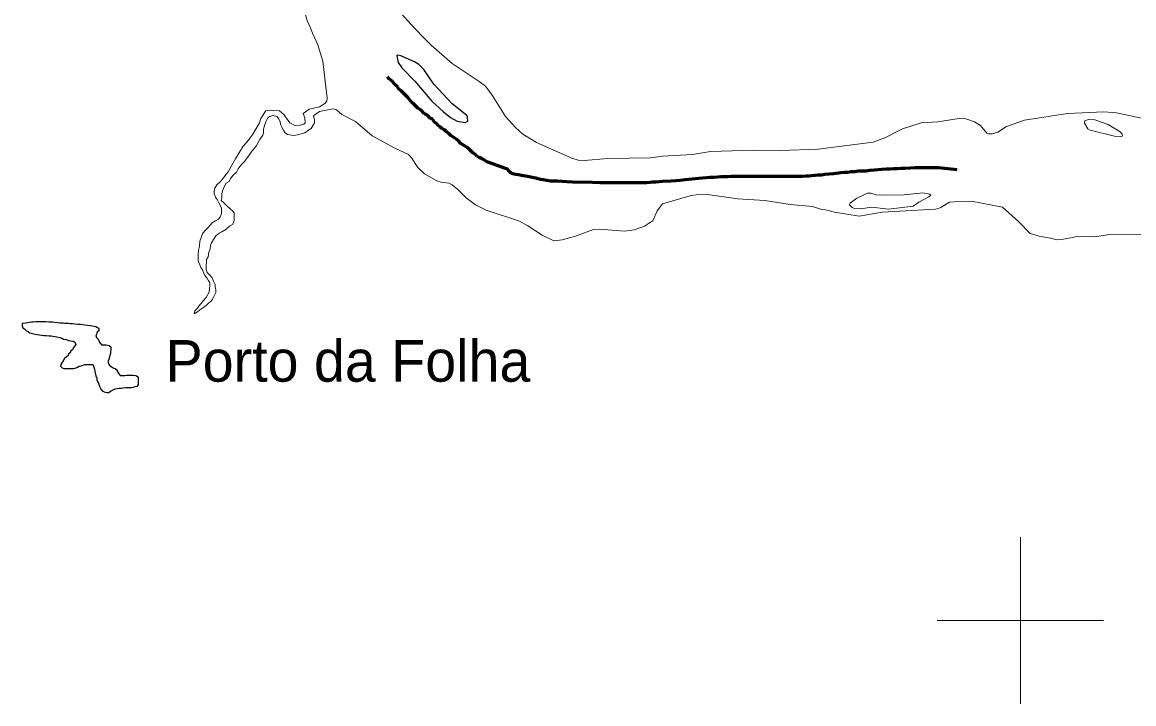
# Model space of a CAD drawing. Extents: x 553962 to 842807, y 8883888 to 9032388.
# Drawn here: x 687999 to 701363, y 8899000 to 8907189 of the extents above; entities that cross this region are included whole.
import ezdxf

# ---------------------------------------------------------------- set-up
doc = ezdxf.new("R2010")
doc.units = 0
doc.header["$LTSCALE"] = 200
doc.linetypes.add('LONG_DASH_SHORT_DASH', pattern=[9.9, 6, -1.2, 1.5, -1.2])
for name, color, linetype, lineweight in [('2', 7, 'Continuous', 13), ('21', 7, 'Continuous', 25), ('24', 7, 'Continuous', 25), ('25', 7, 'Continuous', 13), ('7', 7, 'Continuous', 90)]:
    doc.layers.add(name, color=color, linetype=linetype, lineweight=lineweight)
doc.layers.add('41', color=7, linetype='Continuous')

msp = doc.modelspace()

# ---------------------------------------------------------------- linework, layer by layer
at = {"layer": '2'}
for p, q in [((700000, 8899000), (700000, 8901000)), ((699000, 8900000), (701000, 8900000))]:
    msp.add_line(p, q, dxfattribs=at)
at = {"layer": '21', "lineweight": 13}
for points in [[(687999.3, 8903568.5), (688042.6, 8903573.7), (688065.5, 8903578.8), (688085.8, 8903581.3), (688111.3, 8903586.4), (688131.6, 8903586.4), (688162.2, 8903589), (688197.8, 8903589), (688218.1, 8903589), (688251.2, 8903589), (688281.8, 8903589), (688319.9, 8903586.4), (688363.2, 8903583.9), (688386.1, 8903581.3), (688424.2, 8903578.8), (688454.8, 8903573.7), (688490.4, 8903573.7), (688510.8, 8903571.1), (688536.2, 8903568.6), (688556.6, 8903568.6), (688576.9, 8903566), (688602.4, 8903563.4), (688632.9, 8903560.9), (688666, 8903558.3), (688701.6, 8903555.8), (688722, 8903553.2), (688783, 8903545.6), (688818.7, 8903540.4), (688841.6, 8903537.9), (688861.9, 8903532.8), (688882.3, 8903527.7), (688905.2, 8903517.4), (688925.5, 8903509.8), (688925.5, 8903489.3), (688905.2, 8903471.4), (688895, 8903440.8), (688887.4, 8903420.3), (688895, 8903397.3), (688915.4, 8903376.8), (688928.1, 8903348.7), (688943.4, 8903328.3), (688961.2, 8903307.8), (688984.1, 8903307.8), (689009.6, 8903307.8), (689045.2, 8903300.2), (689068.1, 8903282.3), (689068.1, 8903251.6), (689065.6, 8903231.2), (689065.6, 8903210.7), (689055.4, 8903190.2), (689052.9, 8903167.2), (689037.6, 8903118.7), (689037.6, 8903098.2), (689045.3, 8903077.8), (689068.2, 8903047.1), (689093.6, 8903034.3), (689116.5, 8903024.1), (689139.5, 8903006.2), (689154.7, 8902985.8), (689164.9, 8902965.3), (689185.3, 8902942.3), (689208.2, 8902942.3), (689233.6, 8902942.3), (689254, 8902944.9), (689282, 8902944.9), (689307.4, 8902944.9), (689332.8, 8902944.9), (689365.9, 8902939.8), (689396.5, 8902921.9), (689396.5, 8902886.1), (689396.5, 8902858), (689396.5, 8902837.5), (689383.8, 8902817.1), (689358.3, 8902811.9), (689338, 8902804.3), (689317.6, 8902801.7), (689287.1, 8902799.2), (689266.8, 8902799.2), (689243.8, 8902799.2), (689213.3, 8902796.6), (689193, 8902794.1), (689165, 8902791.5), (689142.1, 8902788.9), (689116.6, 8902783.8), (689093.7, 8902773.6), (689068.3, 8902758.3), (689037.8, 8902740.4), (689017.4, 8902740.4), (688994.5, 8902742.9), (688964, 8902755.7), (688943.6, 8902778.7), (688933.4, 8902804.3), (688923.2, 8902827.3), (688915.6, 8902852.8), (688905.4, 8902873.3), (688895.2, 8902893.7), (688895.2, 8902914.2), (688885, 8902939.7), (688877.4, 8902975.5), (688872.3, 8902996), (688867.2, 8903019)], [(688867.2, 8903019), (688857, 8903054.8), (688849.4, 8903075.2), (688826.5, 8903077.8), (688806.1, 8903077.8), (688775.6, 8903077.8), (688752.7, 8903075.2), (688732.3, 8903067.6), (688706.9, 8903062.4), (688684, 8903054.8), (688663.6, 8903044.5), (688635.6, 8903034.3), (688615.3, 8903029.2), (688587.3, 8903026.7), (688556.8, 8903026.7), (688531.3, 8903026.7), (688500.8, 8903029.2), (688480.4, 8903036.9), (688457.5, 8903054.8), (688462.6, 8903077.8), (688475.3, 8903098.2), (688490.6, 8903121.2), (688508.4, 8903146.8), (688531.3, 8903167.2), (688551.6, 8903185.1), (688556.7, 8903205.6), (688577.1, 8903218.4), (688584.7, 8903238.8), (688605, 8903254.2), (688617.7, 8903279.7), (688633, 8903300.2), (688643.2, 8903320.6), (688633, 8903346.2), (688612.6, 8903356.4), (688584.6, 8903361.5), (688556.6, 8903366.6), (688528.6, 8903376.8), (688495.6, 8903381.9), (688475.2, 8903392.2), (688452.3, 8903399.8), (688416.7, 8903407.5), (688396.3, 8903412.6), (688368.3, 8903417.7), (688348, 8903420.3), (688322.5, 8903422.8), (688286.9, 8903425.4), (688264, 8903425.4), (688230.9, 8903430.5), (688208, 8903433.1), (688177.5, 8903438.2), (688154.6, 8903440.7), (688124.1, 8903448.4), (688091, 8903458.6), (688070.6, 8903471.4), (688050.2, 8903479.1), (688029.9, 8903499.5), (688007, 8903517.4), (687999.3, 8903543), (687999.3, 8903568.5)]]:
    msp.add_lwpolyline(points, dxfattribs=at)
at = {"layer": '21'}
for points in [[(688867.2, 8903019), (688872.3, 8902996), (688877.4, 8902975.5), (688885, 8902939.7), (688895.2, 8902914.2), (688895.2, 8902893.7), (688905.4, 8902873.3), (688915.6, 8902852.8), (688923.2, 8902827.3), (688933.4, 8902804.3), (688943.6, 8902778.7), (688964, 8902755.7), (688994.5, 8902742.9), (689017.4, 8902740.4), (689037.8, 8902740.4), (689068.3, 8902758.3), (689093.7, 8902773.6), (689116.6, 8902783.8), (689142.1, 8902788.9), (689165, 8902791.5), (689193, 8902794.1), (689213.3, 8902796.6), (689243.8, 8902799.2), (689266.8, 8902799.2), (689287.1, 8902799.2), (689317.6, 8902801.7), (689338, 8902804.3), (689358.3, 8902811.9), (689383.8, 8902817.1), (689396.5, 8902837.5), (689396.5, 8902858), (689396.5, 8902886.1), (689396.5, 8902921.9), (689365.9, 8902939.8), (689332.8, 8902944.9), (689307.4, 8902944.9), (689282, 8902944.9), (689254, 8902944.9), (689233.6, 8902942.3), (689208.2, 8902942.3), (689185.3, 8902942.3), (689164.9, 8902965.3), (689154.7, 8902985.8), (689139.5, 8903006.2), (689116.5, 8903024.1), (689093.6, 8903034.3), (689068.2, 8903047.1), (689045.3, 8903077.8), (689037.6, 8903098.2), (689037.6, 8903118.7), (689052.9, 8903167.2), (689055.4, 8903190.2), (689065.6, 8903210.7), (689065.6, 8903231.2), (689068.1, 8903251.6), (689068.1, 8903282.3), (689045.2, 8903300.2), (689009.6, 8903307.8), (688984.1, 8903307.8), (688961.2, 8903307.8), (688943.4, 8903328.3), (688928.1, 8903348.7), (688915.4, 8903376.8), (688895, 8903397.3), (688887.4, 8903420.3), (688895, 8903440.8), (688905.2, 8903471.4), (688925.5, 8903489.3), (688925.5, 8903509.8), (688905.2, 8903517.4), (688882.3, 8903527.7), (688861.9, 8903532.8), (688841.6, 8903537.9), (688818.7, 8903540.4), (688783, 8903545.6), (688722, 8903553.2), (688701.6, 8903555.8), (688666, 8903558.3), (688632.9, 8903560.9), (688602.4, 8903563.4), (688576.9, 8903566), (688556.6, 8903568.6), (688536.2, 8903568.6), (688510.8, 8903571.1), (688490.4, 8903573.7), (688454.8, 8903573.7), (688424.2, 8903578.8), (688386.1, 8903581.3), (688363.2, 8903583.9), (688319.9, 8903586.4), (688281.8, 8903589), (688251.2, 8903589), (688218.1, 8903589), (688197.8, 8903589), (688162.2, 8903589), (688131.6, 8903586.4), (688111.3, 8903586.4), (688085.8, 8903581.3), (688065.5, 8903578.8), (688042.6, 8903573.7), (687999.3, 8903568.5)], [(687999.3, 8903568.5), (687999.3, 8903543), (688007, 8903517.4), (688029.9, 8903499.5), (688050.2, 8903479.1), (688070.6, 8903471.4), (688091, 8903458.6), (688124.1, 8903448.4), (688154.6, 8903440.7), (688177.5, 8903438.2), (688208, 8903433.1), (688230.9, 8903430.5), (688264, 8903425.4), (688286.9, 8903425.4), (688322.5, 8903422.8), (688348, 8903420.3), (688368.3, 8903417.7), (688396.3, 8903412.6), (688416.7, 8903407.5), (688452.3, 8903399.8), (688475.2, 8903392.2), (688495.6, 8903381.9), (688528.6, 8903376.8), (688556.6, 8903366.6), (688584.6, 8903361.5), (688612.6, 8903356.4), (688633, 8903346.2), (688643.2, 8903320.6), (688633, 8903300.2), (688617.7, 8903279.7), (688605, 8903254.2), (688584.7, 8903238.8), (688577.1, 8903218.4), (688556.7, 8903205.6), (688551.6, 8903185.1), (688531.3, 8903167.2), (688508.4, 8903146.8), (688490.6, 8903121.2), (688475.3, 8903098.2), (688462.6, 8903077.8), (688457.5, 8903054.8), (688480.4, 8903036.9), (688500.8, 8903029.2), (688531.3, 8903026.7), (688556.8, 8903026.7), (688587.3, 8903026.7), (688615.3, 8903029.2), (688635.6, 8903034.3), (688663.6, 8903044.5), (688684, 8903054.8), (688706.9, 8903062.4), (688732.3, 8903067.6), (688752.7, 8903075.2), (688775.6, 8903077.8), (688806.1, 8903077.8), (688826.5, 8903077.8), (688849.4, 8903075.2), (688857, 8903054.8), (688867.2, 8903019)]]:
    msp.add_lwpolyline(points, dxfattribs=at)
at = {"layer": '24'}
msp.add_lwpolyline([(692949.1, 8906444.8), (692825.9, 8906621.7), (692768.5, 8906681.2), (692716.6, 8906713.2), (692549.3, 8906785.2), (692516.7, 8906791.5), (692502.1, 8906785.4), (692518.4, 8906705.4), (692562.6, 8906642), (692720.7, 8906481.3), (692924.1, 8906239.9), (693063.6, 8906110.7), (693147.4, 8906045), (693227.3, 8906002.2), (693327.7, 8905986.2), (693357, 8906001.2), (693353.1, 8906048.7), (693342.8, 8906070), (693166.4, 8906209.1)], close=True, dxfattribs=at)
at = {"layer": '25'}
for points in [[(692044.8, 8908056.7), (692052.8, 8908026.7), (692050.7, 8907961), (692118.3, 8907868.3), (692160.1, 8907748.4), (692220.3, 8907669.3), (692364.9, 8907535.6), (692534.1, 8907312.8), (692551.5, 8907299.7), (692676.4, 8907162.1)], [(691462.3, 8907129.9), (691427, 8907209), (691331.2, 8907539.4), (691281.4, 8907685.4)], [(692676.4, 8907162.1), (692807.4, 8907022.5), (692915.7, 8906912.1), (693169.8, 8906693.4), (693492.8, 8906479), (693569.9, 8906419.6), (693650.4, 8906314.4), (693809.1, 8906055.6), (693809.1, 8906055.6), (693928.4, 8905925.4), (694016.8, 8905845.3), (694182.1, 8905744), (694607.4, 8905554.6), (694682.1, 8905531.8), (694755.6, 8905527.6), (695038, 8905553.4), (695553.9, 8905557.9), (695698.2, 8905581.4), (696059.6, 8905599.2), (696272.7, 8905636.6), (696786.4, 8905651), (697116.6, 8905647.9), (697567.1, 8905664.3), (698229, 8905748.8), (698370.6, 8905800.9), (698581.3, 8905906.7), (698805.8, 8905980.6), (699008.1, 8905992.8), (699263.6, 8906033.6), (699343.2, 8906026.8), (699449.5, 8905993.7), (699522.1, 8905946.6), (699595.2, 8905855.7), (699617, 8905846.3), (699662.2, 8905846.3), (699730.1, 8905870.1)], [(690770.2, 8905843.2), (690852, 8905982.1), (690868.1, 8906034.4), (690928, 8906123.4), (690992.1, 8906133.5), (691093.1, 8906124.6), (691142.8, 8906079.2), (691216.8, 8905979), (691277.6, 8905948.2), (691342.5, 8905951.8), (691386.5, 8905966.2), (691399.8, 8905981.8), (691397.7, 8906042.2), (691378.7, 8906092.7), (691448.3, 8906144.9), (691574.6, 8906171.9), (691637.5, 8906214.2), (691659.8, 8906239.5), (691666.5, 8906276.9), (691614.3, 8906720.4), (691553.2, 8906917.7), (691488.1, 8907058.8), (691462.3, 8907129.9)], [(691574.8, 8906114.8), (691519.4, 8906081.7), (691502.8, 8906063.3), (691513.3, 8906012.8), (691511.5, 8905978.9), (691473.5, 8905914.1), (691441.2, 8905891.3)], [(694392.3, 8904560.9), (694249.3, 8904629.2), (694079.7, 8904743.6), (693976.2, 8904798), (693575.7, 8904930.8), (693449.1, 8904994.9), (693335.6, 8905079), (693236.3, 8905180.3), (693168.5, 8905236.3), (693127.6, 8905254.1), (693035.4, 8905267.9), (692983.1, 8905283.9), (692837.7, 8905367.1), (692753.6, 8905443.3), (692681.2, 8905561), (692642.1, 8905601), (692477.9, 8905674), (692207.4, 8905825.7), (692006.3, 8905995.8), (691843, 8906078.6), (691777.9, 8906135.4), (691733.2, 8906147.2), (691574.8, 8906114.8)], [(699730.1, 8905870.1), (699833.6, 8905937.4), (700049.1, 8906011), (700564.9, 8906093.9), (701005.2, 8906113.6), (701154.5, 8906101.4), (701659.8, 8905992.8), (701803.5, 8905986.5), (702058.9, 8906003.4), (702175.9, 8905983.8), (702373, 8905910.6), (702436.8, 8905905.5), (702682, 8905912.8), (702942.6, 8905799.8), (703043.5, 8905742.3)], [(691259.2, 8905826.4), (691259.2, 8905826.4), (691190.1, 8905839.8), (691158.9, 8905862.1), (691141.1, 8905891), (691121, 8905926.7), (691103.2, 8905962.3), (691098.7, 8905998), (691080.9, 8906031.4), (691063.1, 8906058.1), (691014, 8906069.2), (691014, 8906069.2), (690976.2, 8906058.1), (690976.2, 8906058.1), (690950.8, 8906042.4), (690932.7, 8905999.2), (690914.6, 8905958.6), (690901.5, 8905902.7), (690898.7, 8905862), (690893.5, 8905831.5), (690857.5, 8905778.3), (690836.9, 8905745.3), (690816.3, 8905709.8), (690790.7, 8905676.9), (690759.9, 8905638.9), (690736.8, 8905603.4), (690706, 8905562.8), (690670.1, 8905517.2), (690641.9, 8905486.9), (690618.8, 8905459), (690595.7, 8905428.6), (690575.1, 8905388), (690536.7, 8905350.1), (690503.4, 8905312.1), (690485.4, 8905276.6), (690449.6, 8905256.4), (690436.7, 8905228.5), (690418.7, 8905190.4), (690405.7, 8905157.4), (690397.9, 8905129.5), (690397.6, 8905081.1), (690392.3, 8905048.1), (690422.7, 8905017.4), (690453, 8904989.3), (690498.6, 8904945.8), (690526.4, 8904922.7), (690546.6, 8904897.2), (690546.1, 8904820.8), (690543.3, 8904787.8), (690525.4, 8904759.9), (690492.1, 8904737.2), (690446.1, 8904699.3), (690400.1, 8904671.6), (690366.9, 8904653.9), (690328.6, 8904623.6), (690300.3, 8904580.5), (690274.6, 8904539.9), (690261.7, 8904512), (690258.8, 8904461.2), (690240.8, 8904428.2), (690240.6, 8904397.7), (690232.8, 8904369.7), (690214.8, 8904339.3), (690214.6, 8904308.8), (690211.8, 8904260.4), (690211.5, 8904219.8), (690221.5, 8904181.5), (690251.8, 8904155.9), (690282.1, 8904117.6), (690297.2, 8904079.4), (690317.2, 8904038.6), (690319.6, 8904010.6), (690327, 8903972.4), (690326.8, 8903941.8), (690311.3, 8903908.9), (690288.2, 8903863.2), (690267.6, 8903835.3), (690239.5, 8903812.6), (690211.3, 8903787.3), (690183.2, 8903767.1), (690134.7, 8903731.8), (690106.5, 8903709), (690068.2, 8903683.8), (690073.5, 8903719.4), (690106.8, 8903752.2), (690129.9, 8903787.7), (690155.5, 8903813), (690176.1, 8903840.9), (690211.9, 8903881.4), (690230, 8903916.9), (690248, 8903947.4), (690250.8, 8903988), (690256.1, 8904026.2), (690256.3, 8904059.2), (690236.2, 8904089.9), (690218.5, 8904118), (690195.8, 8904146.1), (690180.7, 8904174.1), (690165.7, 8904212.4), (690148.1, 8904243), (690133, 8904273.6)], [(690133, 8904273.6), (690112.9, 8904319.5), (690113.4, 8904393.3), (690118.8, 8904446.7), (690131.9, 8904502.6), (690134.8, 8904558.5), (690153, 8904614.4), (690171, 8904655), (690204.3, 8904690.4), (690235.1, 8904723.3), (690260.7, 8904751.2), (690283.8, 8904779), (690322.1, 8904801.7), (690360.4, 8904821.8), (690378.3, 8904849.7), (690396.4, 8904887.8), (690396.8, 8904953.9), (690381.7, 8904982), (690361.6, 8905017.7), (690341.5, 8905058.6), (690323.9, 8905086.6), (690306.3, 8905127.4), (690306.6, 8905168.1), (690314.4, 8905193.5), (690340.1, 8905236.6), (690373.4, 8905267), (690409.2, 8905307.5), (690440, 8905348), (690475.9, 8905391.1), (690494, 8905426.6), (690519.7, 8905469.7), (690566, 8905556), (690657.5, 8905699.5), (690657.5, 8905699.5), (690702.1, 8905750.7), (690702.1, 8905750.7), (690746.6, 8905810.9), (690770.2, 8905843.2)], [(691441.2, 8905891.3), (691395.3, 8905858.9), (691308.5, 8905834.7), (691259.2, 8905826.4)], [(697658.8, 8904933.3), (697614.4, 8904938.5), (697502.5, 8904976.8), (697230.9, 8904997.9), (696928.2, 8905046.6), (696603.4, 8905069), (696240.1, 8905118.1), (696100.1, 8905116.6), (696040.6, 8905107), (695698.7, 8905008.5), (695631.9, 8904924.3), (695580.3, 8904801.6), (695529.7, 8904770.2)], [(700224.1, 8904617.8), (700117.5, 8904650.2), (699976.3, 8904795.3), (699784.6, 8904967), (699413.2, 8905038.8), (699203.8, 8905030.7), (699146, 8905026.8), (699035.3, 8904960.2), (698980, 8904944.5), (698337.8, 8904907.7), (698063.3, 8904859.2), (697765.1, 8904905.4), (697658.8, 8904933.3)], [(695529.7, 8904770.2), (695479.1, 8904738.8), (695358.2, 8904694.2), (695244.6, 8904680.4), (694936.5, 8904701), (694868.4, 8904699.3), (694652.2, 8904617.7), (694490.8, 8904574.4), (694392.3, 8904560.9)], [(700368.5, 8904593.8), (700361.3, 8904595.9), (700224.1, 8904617.8)], [(701498, 8904635.9), (701073.3, 8904639.9), (700893.6, 8904612.2), (700683.7, 8904613.8), (700499, 8904578.5), (700435.5, 8904574.2), (700368.5, 8904593.8)]]:
    msp.add_lwpolyline(points, dxfattribs=at)
for points in [[(692949.1, 8906444.8), (692825.9, 8906621.7), (692768.5, 8906681.2), (692716.6, 8906713.2), (692549.3, 8906785.2), (692516.7, 8906791.5), (692502.1, 8906785.4), (692518.4, 8906705.4), (692562.6, 8906642), (692720.7, 8906481.3), (692924.1, 8906239.9), (693063.6, 8906110.7), (693147.4, 8906045), (693227.3, 8906002.2), (693327.7, 8905986.2), (693357, 8906001.2), (693353.1, 8906048.7), (693342.8, 8906070), (693166.4, 8906209.1)], [(700838.5, 8905891.3), (701132.3, 8905819.6), (701206.6, 8905813.1), (701222.7, 8905818.2), (701228.3, 8905829.3), (701220.6, 8905851.5), (701199.7, 8905872.4), (701053.6, 8905962.1), (700895.4, 8906014.9), (700818.6, 8906021.5), (700774.5, 8906004.3), (700770.3, 8905978.1), (700810.1, 8905908.9)], [(698388.1, 8905109.3), (698266.4, 8905115), (698201.6, 8905136.8), (698161, 8905135.9), (698032.8, 8905076.5), (697953.2, 8905013.6), (697944, 8904996.2), (697979.2, 8904962.2), (698006.7, 8904952.9), (698079.2, 8904948.8), (698215.6, 8904965.4), (698416.1, 8904942.8), (698710.2, 8904978.5), (698778.6, 8905025.1), (698900.2, 8905090.5), (698922.8, 8905112.6), (698909.9, 8905123.1), (698826.8, 8905137.9), (698603.2, 8905114.8)]]:
    msp.add_lwpolyline(points, close=True, dxfattribs=at)
at = {"layer": '7', "linetype": 'LONG_DASH_SHORT_DASH', "lineweight": 60}
for points in [[(693130.7, 8905846.2), (693095, 8905876.9), (693074.7, 8905894.8), (693044.1, 8905912.6), (693023.8, 8905933.1), (693000.9, 8905948.4), (692983.1, 8905968.9), (692955.1, 8905989.3), (692934.7, 8906022.6), (692904.1, 8906037.9), (692871.1, 8906073.7), (692830.3, 8906094.1), (692797.2, 8906132.5), (692754, 8906155.5), (692713.2, 8906198.9), (692680.2, 8906229.6), (692634.3, 8906283.3), (692593.6, 8906324.2), (692550.3, 8906370.2), (692522.3, 8906390.6), (692509.6, 8906411.1), (692476.5, 8906446.9), (692448.5, 8906480.1), (692412.9, 8906510.8), (692392.5, 8906531.2)], [(694492.2, 8905273.6), (694436.2, 8905278.7), (694392.9, 8905278.7), (694352.2, 8905281.3), (694260.6, 8905294.1), (694235.2, 8905299.2), (694197, 8905306.9), (694176.7, 8905314.5), (694151.2, 8905319.6), (694115.6, 8905327.3), (694074.9, 8905335), (694044.3, 8905340.1), (694003.6, 8905347.8), (693965.4, 8905355.4), (693932.4, 8905360.5), (693912, 8905363.1), (693881.5, 8905373.3), (693861.1, 8905391.2), (693830.6, 8905429.6), (693810.2, 8905432.1), (693619.3, 8905498.6), (693596.4, 8905508.8), (693573.5, 8905521.6), (693553.2, 8905534.3), (693522.6, 8905552.2), (693494.6, 8905562.5), (693466.6, 8905580.3), (693448.8, 8905600.8), (693418.3, 8905618.7), (693382.7, 8905654.5), (693349.6, 8905685.2), (693324.1, 8905700.5), (693270.7, 8905733.7), (693240.1, 8905766.9), (693212.1, 8905787.4), (693153.6, 8905828.3), (693130.7, 8905846.2)], [(699241.8, 8905417.5), (699018.7, 8905439.9), (698972.9, 8905439.9), (698924.6, 8905439.9), (698871.2, 8905439.9), (698799.9, 8905439.9), (698733.8, 8905439.9), (698675.2, 8905434.8), (698609.1, 8905432.2), (698563.3, 8905432.2), (698520, 8905429.6), (698474.2, 8905429.6), (698431, 8905422), (698387.7, 8905422), (698331.7, 8905419.4), (698247.8, 8905411.7), (698191.8, 8905409.2), (698140.9, 8905401.5), (698092.6, 8905401.5), (698049.3, 8905399), (698008.6, 8905391.3), (697970.4, 8905391.3), (697922.1, 8905383.6), (697886.5, 8905383.6), (697843.2, 8905378.5), (697754.2, 8905368.3), (697700.7, 8905363.2), (697649.8, 8905358.1), (697609.1, 8905352.9), (697565.9, 8905350.4)], [(697565.9, 8905350.4), (697527.7, 8905347.8), (697489.5, 8905342.7), (697456.5, 8905340.2), (697420.8, 8905337.6), (697380.1, 8905335), (697336.9, 8905335), (697280.9, 8905335), (697230, 8905335), (697186.8, 8905335), (697148.6, 8905335), (697105.3, 8905335), (697082.4, 8905335), (697046.8, 8905335), (697011.2, 8905335), (696990.8, 8905335), (696957.7, 8905335), (696934.8, 8905335), (696896.7, 8905335), (696876.3, 8905335), (696820.3, 8905335), (696772, 8905335), (696721.1, 8905335), (696670.2, 8905335), (696624.4, 8905335), (696578.6, 8905335), (696520.1, 8905335), (696481.9, 8905332.5), (696438.7, 8905332.5), (696398, 8905329.9), (696359.8, 8905327.3), (696314, 8905324.8), (696265.7, 8905322.2), (696227.5, 8905319.7), (696176.6, 8905317.1), (696135.9, 8905312), (696095.2, 8905306.9), (696054.5, 8905304.3), (696013.8, 8905299.2), (695970.5, 8905294.1), (695906.9, 8905289), (695858.6, 8905283.9), (695800, 8905281.3), (695698.3, 8905273.7), (695657.6, 8905271.1), (695616.8, 8905268.5), (695578.7, 8905268.5), (695548.1, 8905263.4), (695510, 8905260.9), (695464.2, 8905260.9), (695426, 8905260.9), (695377.7, 8905260.9), (695339.5, 8905260.9), (695293.7, 8905260.9), (695242.8, 8905260.9), (695194.5, 8905260.9), (695143.6, 8905260.9), (695097.8, 8905260.9), (695052, 8905260.9), (695001.1, 8905260.9), (694945.1, 8905260.9), (694856, 8905263.4), (694614.3, 8905268.5), (694545.6, 8905271.1), (694492.2, 8905273.6)]]:
    msp.add_lwpolyline(points, dxfattribs=at)

# ---------------------------------------------------------------- texts
at = {"layer": '41'}
msp.add_text('Porto da Folha', height=500, dxfattribs=at).set_placement((689722.9, 8902870))

doc.saveas('drawing.dxf')
